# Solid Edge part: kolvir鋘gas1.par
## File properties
Author: Türk
Template: Iso Part.par
Last saved by: Türk
Revision: 4
Application: Solid Edge
Accuracy: 0,990
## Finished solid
Body 1: solid body, 4 faces, 4 edges, 0 vertices.
  Faces by surface: cylinder 2, plane 2
  Edges by curve: circle 4
Bounding box of the edges (mm): 88.000 x 2.500 x 88.000, from (-44, 0, -44) to (44, 2.5, 44).
Cylindrical faces by radius (mm): R41.5 x1, R44 x1
Planar faces by outward normal: +y 1, -y 1
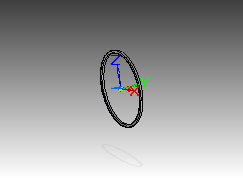
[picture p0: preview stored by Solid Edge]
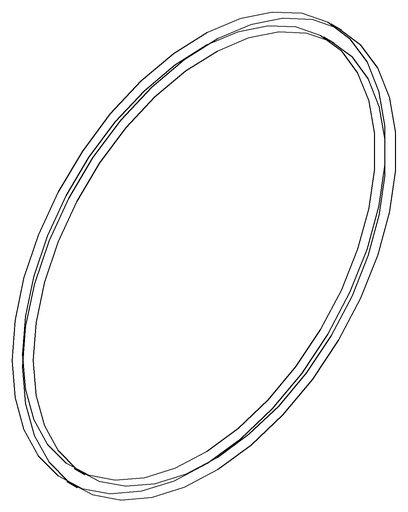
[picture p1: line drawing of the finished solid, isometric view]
